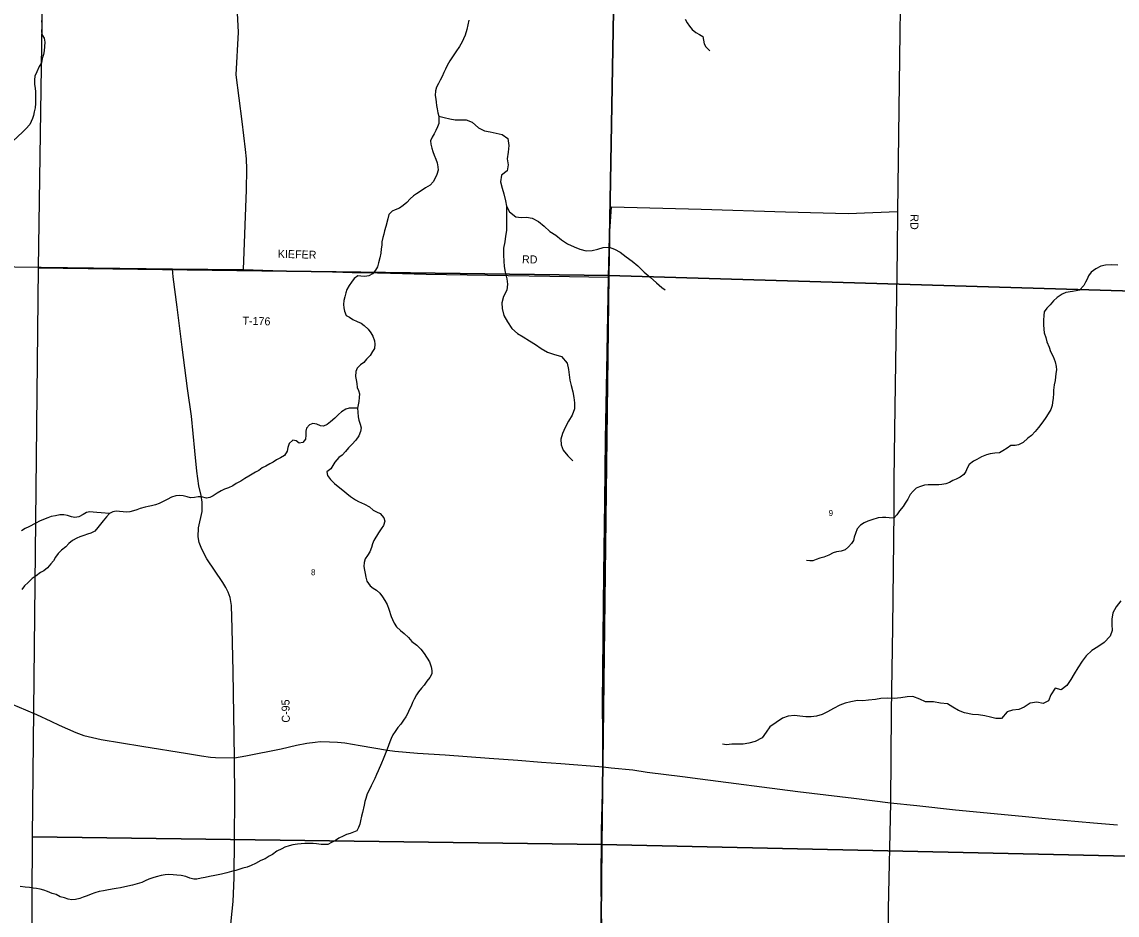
# Model space of a CAD drawing. Extents: x 1312308 to 1684953, y 460642 to 865172.
# Drawn here: x 1416487 to 1426746, y 597865 to 606234 of the extents above; entities that cross this region are included whole.
import ezdxf

# ---------------------------------------------------------------- set-up
doc = ezdxf.new("R2010")
doc.units = 0
for name, color, linetype in [('GM_X_County_Road', 7, 'Continuous'), ('GM_X_County_Road_Text', 7, 'Continuous'), ('GM_X_Minor_River', 7, 'Continuous'), ('GM_X_Section', 7, 'Continuous'), ('GM_X_Section_Text', 7, 'Continuous'), ('GM_X_State_Route', 7, 'Continuous'), ('GM_X_Township_Road', 7, 'Continuous'), ('GM_X_Township_Road_Text', 7, 'Continuous')]:
    doc.layers.add(name, color=color, linetype=linetype)

msp = doc.modelspace()

# ---------------------------------------------------------------- linework, layer by layer
at = {"layer": 'GM_X_County_Road'}
msp.add_lwpolyline([(1418435, 597690), (1418465, 597994), (1418475, 598214), (1418479, 598586), (1418481, 598954), (1418479, 599340), (1418466, 600148), (1418458, 600552), (1418450, 600765), (1418438, 600841), (1418420, 600892), (1418398, 600934), (1418368, 600982), (1418220, 601202), (1418173, 601294), (1418148, 601355), (1418139, 601409), (1418140, 601493), (1418174, 601648), (1418175, 601733), (1418166, 601798), (1418144, 601888), (1418125, 602025), (1418108, 602216), (1418074, 602540), (1418039, 602799), (1417988, 603185), (1417941, 603562), (1417904, 603845), (1417899, 603921), (1418564, 603914), (1418590, 604660), (1418595, 604855), (1418591, 604950), (1418582, 605039), (1418551, 605302), (1418495, 605739), (1418515, 606139), (1418507, 606316)], dxfattribs=at)
at = {"layer": 'GM_X_Minor_River'}
for points in [[(1416669, 606248), (1416672, 606211), (1416672, 606181), (1416669, 606149), (1416674, 606115), (1416694, 606081), (1416701, 606044), (1416700, 606002), (1416695, 605964), (1416688, 605928), (1416678, 605892), (1416669, 605852), (1416648, 605815), (1416627, 605767), (1416608, 605727), (1416605, 605691), (1416605, 605649), (1416610, 605613), (1416613, 605579), (1416614, 605546), (1416613, 605470), (1416610, 605428), (1416603, 605392), (1416597, 605358), (1416586, 605328), (1416561, 605273), (1416524, 605233), (1416493, 605200), (1416402, 605118)], [(1420675, 606250), (1420664, 606208), (1420655, 606162), (1420638, 606110), (1420623, 606076), (1420610, 606046), (1420585, 606002), (1420552, 605953), (1420521, 605907), (1420494, 605870), (1420471, 605826), (1420455, 605792), (1420440, 605760), (1420423, 605723), (1420406, 605689), (1420388, 605657), (1420371, 605621), (1420362, 605589), (1420359, 605545), (1420363, 605511), (1420366, 605481), (1420371, 605451), (1420377, 605419), (1420384, 605382), (1420391, 605350), (1420393, 605320), (1420392, 605282), (1420381, 605252), (1420365, 605218), (1420350, 605186), (1420331, 605155), (1420315, 605121), (1420318, 605087), (1420327, 605052), (1420337, 605020), (1420350, 604984), (1420365, 604949), (1420376, 604913), (1420384, 604875), (1420385, 604845), (1420374, 604805), (1420355, 604765), (1420339, 604735), (1420312, 604704), (1420269, 604678), (1420237, 604657), (1420184, 604624), (1420154, 604604), (1420123, 604575), (1420094, 604543), (1420057, 604514), (1420023, 604490)], [(1422701, 606260), (1422720, 606226), (1422742, 606193), (1422765, 606162), (1422801, 606136), (1422834, 606115), (1422864, 606096), (1422871, 606062), (1422877, 606030), (1422894, 606000), (1422931, 605963)], [(1420391, 605350), (1420443, 605339), (1420494, 605326), (1420546, 605315), (1420599, 605318), (1420649, 605317), (1420706, 605296), (1420763, 605242), (1420821, 605213), (1420873, 605204), (1420931, 605190), (1420987, 605179), (1421040, 605140), (1421049, 605076), (1421043, 605012), (1421034, 604950), (1421041, 604894), (1421032, 604840), (1420979, 604799), (1420969, 604737), (1420986, 604676), (1421001, 604622), (1421016, 604558), (1421025, 604507), (1421026, 604457), (1421025, 604393), (1421027, 604341), (1421026, 604279), (1421017, 604227), (1421010, 604173), (1420997, 604113), (1420997, 604047), (1421000, 603993), (1421003, 603941), (1421014, 603890), (1421029, 603826), (1421036, 603776), (1421029, 603720), (1420999, 603660), (1420984, 603603), (1420985, 603548), (1421002, 603482), (1421035, 603423), (1421077, 603360), (1421130, 603313), (1421182, 603282), (1421241, 603246), (1421299, 603213), (1421352, 603174), (1421410, 603141), (1421467, 603121), (1421543, 603098), (1421596, 603038), (1421607, 602978), (1421612, 602928), (1421619, 602878), (1421632, 602827), (1421649, 602769), (1421657, 602714), (1421662, 602664), (1421663, 602610), (1421642, 602548), (1421607, 602493), (1421577, 602434), (1421550, 602378), (1421535, 602326), (1421538, 602272), (1421557, 602220), (1421600, 602167), (1421647, 602122)], [(1420023, 604490), (1419984, 604473), (1419954, 604461), (1419925, 604430), (1419914, 604390), (1419897, 604318), (1419882, 604278), (1419877, 604246), (1419867, 604214), (1419860, 604172), (1419857, 604142), (1419853, 604108), (1419848, 604068), (1419839, 604022), (1419828, 603976), (1419817, 603940), (1419798, 603907), (1419771, 603873), (1419737, 603854), (1419699, 603850), (1419663, 603853), (1419633, 603856), (1419600, 603830), (1419575, 603796), (1419553, 603763), (1419532, 603727), (1419521, 603695), (1419512, 603657), (1419504, 603625), (1419499, 603587), (1419502, 603555), (1419510, 603523), (1419525, 603484), (1419555, 603466), (1419586, 603445), (1419626, 603426), (1419664, 603412), (1419693, 603389), (1419729, 603356), (1419756, 603320), (1419774, 603289), (1419789, 603247), (1419794, 603215), (1419789, 603175), (1419771, 603145), (1419748, 603109), (1419715, 603074), (1419690, 603042), (1419658, 603021), (1419629, 602991), (1419614, 602959), (1419613, 602913), (1419619, 602881), (1419624, 602845), (1419629, 602810), (1419639, 602780), (1419648, 602748), (1419647, 602714), (1419643, 602678), (1419638, 602646), (1419631, 602614), (1419633, 602576), (1419638, 602535), (1419643, 602503), (1419654, 602465), (1419664, 602431), (1419659, 602395), (1419642, 602357), (1419615, 602315), (1419578, 602276), (1419546, 602244), (1419517, 602209), (1419488, 602175), (1419455, 602152), (1419418, 602110), (1419398, 602077), (1419381, 602045), (1419342, 602019), (1419348, 601983), (1419377, 601947), (1419414, 601910), (1419450, 601881), (1419479, 601860), (1419566, 601787), (1419612, 601756), (1419641, 601739), (1419697, 601714), (1419743, 601689), (1419778, 601660), (1419808, 601644), (1419842, 601627), (1419877, 601588), (1419888, 601556), (1419874, 601516), (1419851, 601484), (1419826, 601447), (1419784, 601375), (1419772, 601345), (1419763, 601309), (1419746, 601270), (1419725, 601236)], [(1421025, 604507), (1421056, 604456), (1421113, 604409), (1421165, 604402), (1421215, 604405), (1421267, 604394), (1421325, 604364), (1421380, 604319), (1421433, 604270), (1421490, 604235), (1421542, 604191), (1421599, 604154), (1421659, 604125), (1421714, 604104), (1421774, 604090), (1421830, 604093), (1421881, 604106), (1421933, 604119), (1421987, 604124), (1422039, 604106), (1422091, 604077), (1422146, 604032), (1422203, 603993), (1422258, 603947), (1422315, 603888), (1422373, 603843), (1422430, 603789), (1422483, 603746), (1422514, 603723)], [(1426752, 603955), (1426692, 603957), (1426637, 603954), (1426595, 603944), (1426546, 603919), (1426504, 603888), (1426479, 603856), (1426466, 603824), (1426450, 603795), (1426435, 603763), (1426394, 603721), (1426362, 603714), (1426327, 603707), (1426267, 603698), (1426233, 603682), (1426186, 603653), (1426151, 603622), (1426118, 603584), (1426088, 603553), (1426063, 603517), (1426060, 603483), (1426057, 603441), (1426056, 603395), (1426059, 603356), (1426063, 603322), (1426078, 603276), (1426087, 603236), (1426110, 603187), (1426123, 603145), (1426146, 603100), (1426167, 603048), (1426177, 603005), (1426178, 602973), (1426173, 602941), (1426166, 602873), (1426157, 602835), (1426152, 602783), (1426149, 602751), (1426146, 602709), (1426142, 602669), (1426137, 602639), (1426124, 602601), (1426101, 602561), (1426078, 602526), (1426050, 602488), (1426010, 602433), (1425980, 602397), (1425945, 602360), (1425910, 602334), (1425865, 602293), (1425823, 602270), (1425792, 602264), (1425752, 602265), (1425716, 602241), (1425675, 602214), (1425645, 602197), (1425602, 602193), (1425556, 602186), (1425522, 602179), (1425477, 602160), (1425431, 602134), (1425400, 602119), (1425359, 602086), (1425343, 602052), (1425330, 602022), (1425311, 601992), (1425277, 601969), (1425240, 601949), (1425206, 601938), (1425175, 601918), (1425141, 601905), (1425105, 601900), (1425075, 601896), (1425041, 601897), (1425007, 601896), (1424976, 601896), (1424942, 601893), (1424896, 601878), (1424863, 601866), (1424837, 601837)], [(1419631, 602614), (1419553, 602615), (1419521, 602606), (1419482, 602582), (1419452, 602555), (1419417, 602522), (1419378, 602488), (1419345, 602461), (1419313, 602445), (1419283, 602448), (1419251, 602464), (1419211, 602471), (1419181, 602458), (1419154, 602428), (1419146, 602398), (1419147, 602362), (1419144, 602324), (1419119, 602292), (1419085, 602287), (1419055, 602308), (1419025, 602316), (1418991, 602285), (1418978, 602245), (1418971, 602213), (1418946, 602173), (1418908, 602150), (1418873, 602130), (1418841, 602109), (1418808, 602093), (1418772, 602072), (1418739, 602055), (1418707, 602031), (1418674, 602016), (1418644, 601996), (1418613, 601979), (1418575, 601955), (1418538, 601930), (1418494, 601909), (1418463, 601887), (1418421, 601870), (1418386, 601857), (1418352, 601841), (1418317, 601820), (1418279, 601794), (1418248, 601779), (1418216, 601773), (1418170, 601784), (1418138, 601785), (1418104, 601778), (1418066, 601774), (1418034, 601783), (1417998, 601792), (1417966, 601796), (1417930, 601795), (1417887, 601780), (1417847, 601760), (1417810, 601739), (1417772, 601722), (1417737, 601708), (1417701, 601699), (1417671, 601693), (1417641, 601686), (1417596, 601675), (1417562, 601663), (1417532, 601652), (1417497, 601644), (1417467, 601639), (1417435, 601643), (1417401, 601648), (1417369, 601649), (1417339, 601645), (1417306, 601628), (1417280, 601596), (1417247, 601559), (1417224, 601529), (1417199, 601497), (1417171, 601464), (1417132, 601444), (1417102, 601433), (1417068, 601422), (1417031, 601410), (1417001, 601397), (1416962, 601375), (1416926, 601348), (1416897, 601316), (1416858, 601285), (1416827, 601252), (1416803, 601220), (1416782, 601184), (1416757, 601155), (1416726, 601119), (1416692, 601092), (1416661, 601076), (1416619, 601045), (1416584, 601019), (1416545, 600980), (1416512, 600950), (1416486, 600917)], [(1424837, 601837), (1424808, 601805), (1424785, 601761), (1424762, 601726), (1424742, 601694), (1424709, 601652), (1424682, 601615), (1424655, 601585), (1424611, 601586), (1424581, 601589), (1424549, 601589), (1424509, 601588), (1424448, 601569), (1424412, 601556), (1424377, 601542), (1424341, 601519), (1424312, 601485), (1424295, 601441), (1424284, 601406), (1424276, 601376), (1424257, 601346), (1424230, 601316), (1424198, 601289), (1424161, 601275), (1424119, 601268), (1424085, 601261), (1424046, 601237), (1424000, 601220), (1423963, 601211), (1423927, 601196), (1423897, 601184), (1423867, 601185), (1423837, 601187)], [(1417306, 601628), (1417230, 601635), (1417190, 601638), (1417154, 601641), (1417124, 601643), (1417092, 601638), (1417060, 601618), (1417021, 601597), (1416983, 601592), (1416951, 601598), (1416913, 601609), (1416879, 601616), (1416841, 601614), (1416801, 601607), (1416762, 601600), (1416730, 601586), (1416689, 601571), (1416651, 601556), (1416617, 601538), (1416552, 601503), (1416517, 601486), (1416483, 601467)], [(1419725, 601236), (1419703, 601204), (1419694, 601168), (1419691, 601132), (1419697, 601098), (1419702, 601066), (1419709, 601030), (1419719, 600995), (1419748, 600949), (1419777, 600928), (1419809, 600909), (1419841, 600881), (1419866, 600848), (1419887, 600814), (1419909, 600775), (1419924, 600733), (1419946, 600664), (1419958, 600634), (1419975, 600601), (1419997, 600567), (1420034, 600532), (1420067, 600503), (1420107, 600465), (1420140, 600428), (1420186, 600393), (1420223, 600356), (1420254, 600317), (1420305, 600238), (1420322, 600190), (1420327, 600158), (1420327, 600125), (1420308, 600092), (1420281, 600058), (1420254, 600020), (1420230, 599991), (1420203, 599957), (1420182, 599928), (1420161, 599890), (1420145, 599856), (1420132, 599824), (1420115, 599790), (1420102, 599758), (1420082, 599723), (1420061, 599693), (1420038, 599653), (1420007, 599622), (1419982, 599584), (1419962, 599554), (1419945, 599521), (1419932, 599489), (1419920, 599455), (1419907, 599419), (1419890, 599373), (1419871, 599325), (1419856, 599290), (1419823, 599218), (1419808, 599184), (1419793, 599146), (1419776, 599113), (1419759, 599075), (1419741, 599035), (1419722, 599003), (1419709, 598959), (1419700, 598929), (1419692, 598895), (1419676, 598826), (1419669, 598792), (1419660, 598748), (1419652, 598716), (1419641, 598686), (1419624, 598656), (1419592, 598641), (1419562, 598631), (1419529, 598620), (1419497, 598606), (1419457, 598585), (1419424, 598565), (1419387, 598544), (1419353, 598527), (1419291, 598528), (1419247, 598533), (1419215, 598535), (1419177, 598536), (1419137, 598535), (1419102, 598533), (1419068, 598530), (1419024, 598523), (1418990, 598515), (1418951, 598502), (1418921, 598487), (1418874, 598463), (1418834, 598434), (1418803, 598418), (1418765, 598391), (1418726, 598376), (1418675, 598349), (1418635, 598331), (1418596, 598314), (1418556, 598305), (1418490, 598284), (1418451, 598273)], [(1426781, 600809), (1426736, 600752), (1426706, 600697), (1426697, 600639), (1426696, 600589), (1426699, 600531), (1426682, 600479), (1426624, 600420), (1426566, 600379), (1426509, 600344), (1426458, 600295), (1426418, 600244), (1426377, 600181), (1426344, 600126), (1426313, 600072), (1426275, 600017), (1426222, 599976), (1426167, 599991), (1426127, 599930), (1426104, 599872), (1426053, 599849), (1425993, 599861), (1425931, 599850), (1425876, 599813), (1425826, 599792), (1425767, 599786), (1425715, 599771), (1425663, 599708), (1425611, 599707), (1425559, 599720), (1425506, 599733), (1425448, 599742), (1425392, 599746), (1425318, 599759), (1425260, 599781), (1425208, 599812), (1425157, 599845), (1425091, 599852), (1425025, 599864), (1424951, 599864), (1424897, 599889), (1424832, 599912), (1424781, 599909), (1424721, 599901), (1424659, 599896), (1424595, 599899), (1424534, 599895), (1424482, 599886), (1424416, 599879), (1424364, 599874), (1424314, 599875), (1424253, 599863), (1424199, 599852), (1424148, 599831), (1424091, 599802), (1424033, 599771), (1423982, 599744), (1423931, 599728), (1423881, 599723), (1423829, 599722), (1423773, 599729), (1423723, 599734)], [(1423723, 599734), (1423665, 599729), (1423612, 599710), (1423551, 599670), (1423494, 599629), (1423459, 599578), (1423420, 599526), (1423357, 599492), (1423297, 599477), (1423242, 599468), (1423192, 599467), (1423138, 599466), (1423088, 599462), (1423050, 599466)], [(1418451, 598273), (1418405, 598261), (1418356, 598250), (1418326, 598241), (1418294, 598237), (1418244, 598226), (1418205, 598219), (1418165, 598210), (1418127, 598202), (1418097, 598203), (1418061, 598212), (1418023, 598226), (1417979, 598235), (1417937, 598238), (1417903, 598241), (1417863, 598245), (1417829, 598244), (1417791, 598237), (1417746, 598223), (1417714, 598216), (1417677, 598201), (1417641, 598187), (1417609, 598172), (1417568, 598159), (1417524, 598147), (1417478, 598136), (1417409, 598121), (1417371, 598114), (1417333, 598109), (1417282, 598100), (1417250, 598094), (1417212, 598085), (1417171, 598074), (1417137, 598060), (1417097, 598045), (1417062, 598033), (1417030, 598022), (1416990, 598011), (1416955, 598007), (1416919, 598014), (1416886, 598027), (1416846, 598037), (1416808, 598058), (1416770, 598069), (1416726, 598086), (1416693, 598098), (1416659, 598107), (1416623, 598114), (1416591, 598118), (1416557, 598125), (1416517, 598128), (1416471, 598133)]]:
    msp.add_lwpolyline(points, dxfattribs=at)
at = {"layer": 'GM_X_Section'}
for points in [[(1416727, 609576), (1421912, 609528), (1422084, 609519), (1421984, 603859), (1416642, 603929)], [(1422084, 609519), (1427288, 609459), (1427408, 609456), (1427319, 603698), (1421984, 603859)], [(1421984, 603859), (1421918, 598528), (1416586, 598599), (1416642, 603929)], [(1427319, 603698), (1427279, 598407), (1421918, 598528), (1421984, 603859)], [(1416586, 598599), (1421918, 598528), (1421873, 593189), (1416559, 593267)], [(1421918, 598528), (1427279, 598407), (1427213, 593108), (1421873, 593189)]]:
    msp.add_lwpolyline(points, close=True, dxfattribs=at)
at = {"layer": 'GM_X_State_Route'}
for points in [[(1413764, 600822), (1413892, 600776), (1414159, 600679), (1414508, 600552), (1414926, 600401), (1415158, 600318), (1415320, 600266), (1415569, 600180), (1415810, 600086), (1416283, 599888), (1416522, 599790), (1416625, 599745), (1416758, 599683), (1416836, 599644), (1416991, 599576), (1417066, 599547), (1417228, 599510), (1417611, 599448), (1418039, 599378), (1418169, 599356), (1418253, 599344), (1418299, 599341), (1418479, 599340)], [(1418479, 599340), (1418584, 599357), (1418916, 599424), (1419060, 599456), (1419156, 599475), (1419235, 599485), (1419282, 599491), (1419369, 599490), (1419442, 599485), (1419511, 599478), (1419657, 599453), (1419913, 599411), (1419980, 599402), (1420194, 599383), (1420451, 599366), (1420865, 599335), (1421134, 599317), (1421353, 599299), (1421536, 599286), (1421932, 599256), (1422007, 599246), (1422210, 599225), (1422343, 599206), (1422676, 599164), (1422840, 599142), (1423755, 599023), (1424280, 598961), (1424622, 598918), (1424870, 598892), (1425231, 598851), (1425856, 598792), (1426104, 598768), (1426524, 598730), (1426599, 598725), (1426751, 598711)]]:
    msp.add_lwpolyline(points, dxfattribs=at)
at = {"layer": 'GM_X_Township_Road'}
for points in [[(1424714, 606348), (1424711, 606136), (1424690, 604458)], [(1421982, 603842), (1421992, 604226), (1422009, 604502), (1422851, 604480), (1423641, 604456), (1424228, 604440), (1424690, 604458)], [(1424690, 604458), (1424690, 604458), (1424686, 604094), (1424660, 602408), (1424656, 601939), (1424654, 601648), (1424641, 600564), (1424629, 599771), (1424622, 598918), (1424603, 597924), (1424602, 597802), (1424587, 597587), (1424590, 596789), (1424574, 596082), (1424564, 595180), (1424549, 593823)], [(1410959, 603993), (1414941, 603959), (1417899, 603921)], [(1418564, 603914), (1418929, 603903), (1419395, 603891), (1419405, 603891)], [(1419405, 603891), (1419581, 603886), (1419817, 603882), (1419826, 603882)], [(1419826, 603882), (1420273, 603872), (1420847, 603862), (1421432, 603852), (1421982, 603842)], [(1421932, 599256), (1421926, 599851), (1421931, 600463), (1421939, 601066), (1421948, 601737), (1421955, 602324), (1421966, 602967), (1421982, 603842)], [(1421852, 592708), (1421872, 593077), (1421879, 593903), (1421888, 594760), (1421893, 595245), (1421901, 596086), (1421911, 596940), (1421920, 597729), (1421912, 598140), (1421916, 598655), (1421932, 599256)]]:
    msp.add_lwpolyline(points, dxfattribs=at)

# ---------------------------------------------------------------- texts
at = {"layer": 'GM_X_County_Road_Text'}
msp.add_text('C-95', height=75, rotation=91.0293, dxfattribs=at).set_placement((1418997, 599669))
at = {"layer": 'GM_X_Section_Text'}
for s, p in [('9', (1424044, 601605)), ('8', (1419195, 601050))]:
    msp.add_text(s, height=55.3, rotation=0, dxfattribs=at).set_placement(p)
at = {"layer": 'GM_X_Township_Road_Text'}
for s, rotation, p in [('RD', 269.5057, (1424811, 604432)), ('KIEFER', 358.4416, (1418883, 604024)), ('RD', 359.5051, (1421171, 603972)), ('T-176', 358.3272, (1418552, 603398))]:
    msp.add_text(s, height=75, rotation=rotation, dxfattribs=at).set_placement(p)

doc.saveas('drawing.dxf')
